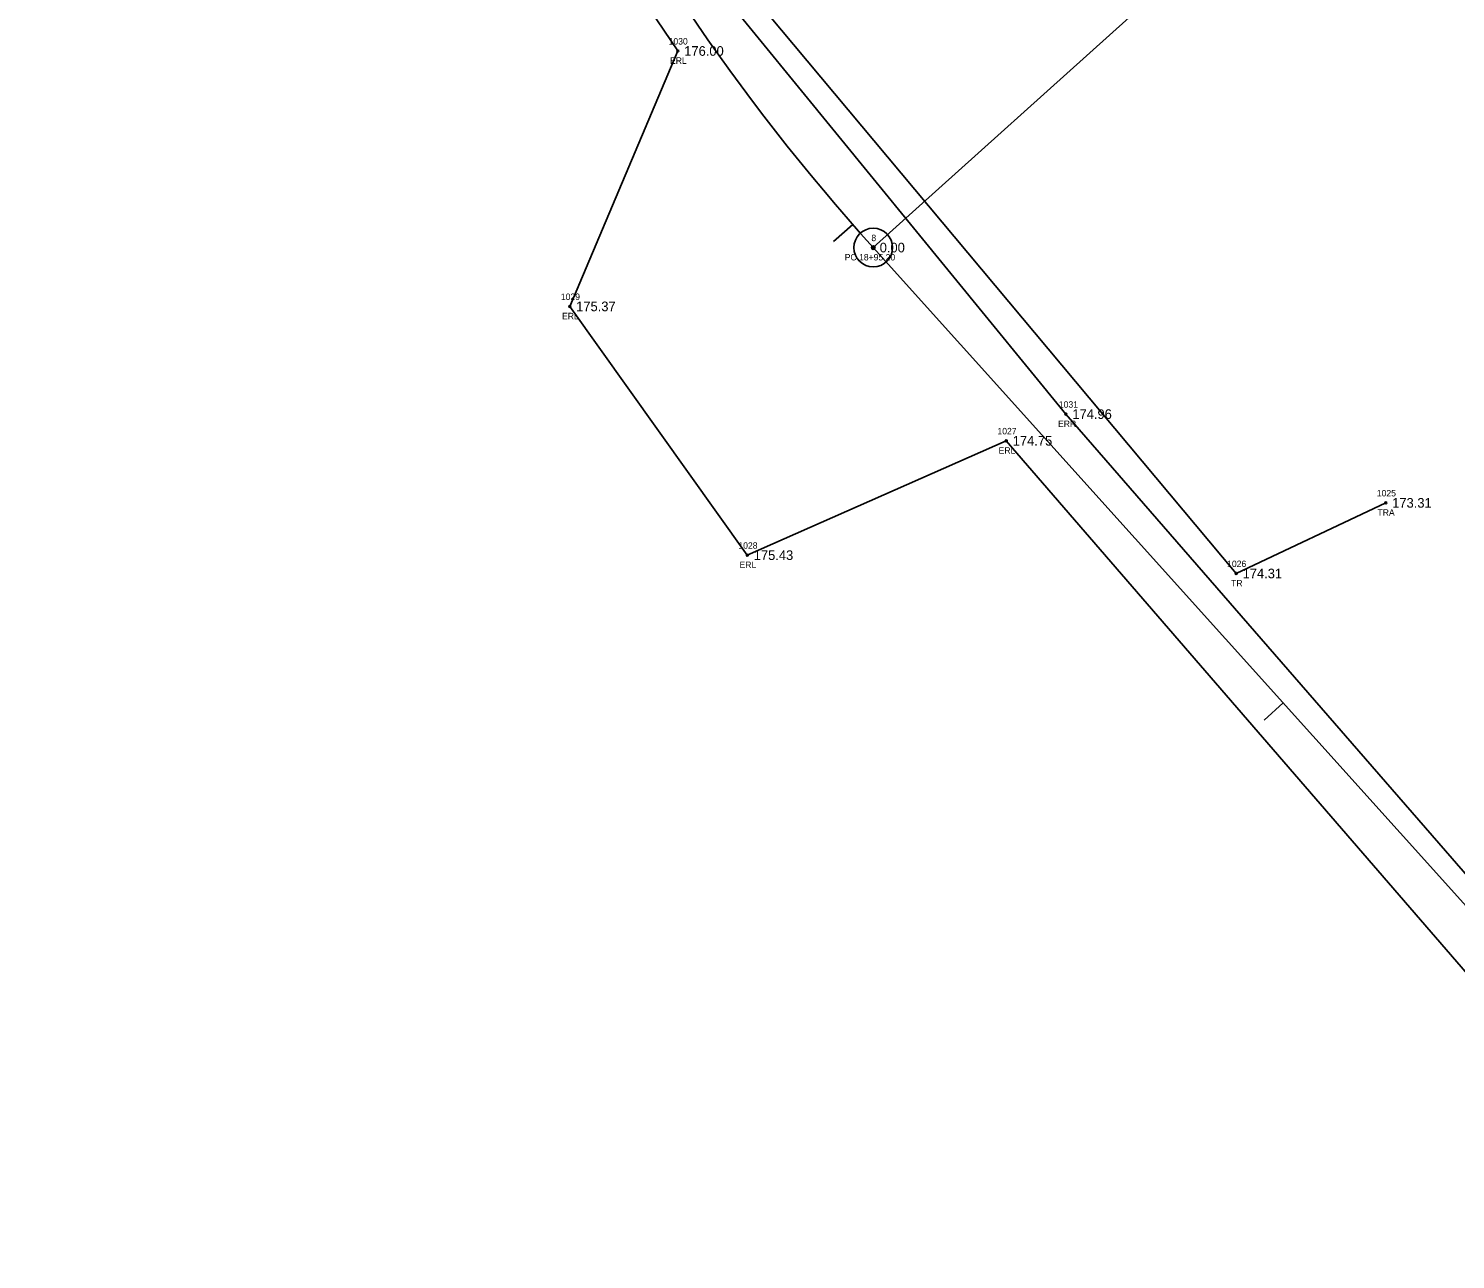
# Model space of a CAD drawing. Extents: x 1970735 to 1971583, y 794736 to 795766.
# Drawn here: x 1970770.6 to 1970992.3, y 795256 to 795447.2 of the extents above; entities that cross this region are included whole.
import ezdxf

# ---------------------------------------------------------------- set-up
doc = ezdxf.new("R2010")
doc.units = 0
for name, color, linetype in [('RD_EX_Road', 7, 'Continuous'), ('RD_EX_Road_txCode', 7, 'Continuous'), ('RD_EX_TX_Road_ELEV', 7, 'Continuous'), ('RD_EX_TX_VEG_ELEV', 7, 'Continuous'), ('RD_EX_VEG', 7, 'Continuous'), ('RD_EX_VEG_txCode', 7, 'Continuous'), ('RD_HC_Cl', 7, 'Continuous'), ('RD_HC_Data', 7, 'Continuous'), ('RD_HC_Data_Tic', 7, 'Continuous'), ('RD_HC_Survey_ELEV', 7, 'Continuous'), ('RD_HC_txCode', 7, 'Continuous'), ('RD_SMD_Locator', 7, 'Continuous')]:
    doc.layers.add(name, color=color, linetype=linetype)

msp = doc.modelspace()

# ---------------------------------------------------------------- linework, layer by layer
at = {"layer": 'RD_EX_Road'}
for points in [[(1971550.5, 794861.13), (1971472.2, 794904.32), (1971401.49, 794943.08), (1971346.58, 794975.73), (1971286.05, 795024.56), (1971217.92, 795079.41), (1971172.76, 795121.06), (1971082.31, 795221.27), (1971017.96, 795288.13), (1970931.75, 795387.33), (1970878.11, 795452.95), (1970856.35, 795489.48), (1970840.29, 795529.45), (1970827.57, 795574.31), (1970814.81, 795635.62), (1970805.04, 795696.13), (1970791.39, 795763.83)], [(1971543.68, 794851.6), (1971507.7, 794872.08), (1971504.76, 794847.96), (1971494.98, 794846.56), (1971488.18, 794883), (1971469.72, 794893.79), (1971395.92, 794934.76), (1971339.47, 794967.38), (1971278.34, 795016.59), (1971212.1, 795072.1), (1971165.04, 795113.96), (1971074.42, 795213.48), (1971010.42, 795281.48), (1970922.49, 795383.19), (1970882.25, 795365.41), (1970854.66, 795404.07), (1970871.45, 795443.76), (1970844.39, 795483.83), (1970828.93, 795526.65), (1970817.76, 795568.61), (1970806.82, 795600.57), (1970787.72, 795602.49), (1970770.58, 795591.56)]]:
    msp.add_lwpolyline(points, dxfattribs=at)
at = {"layer": 'RD_EX_VEG'}
msp.add_lwpolyline([(1970981.44, 795373.54), (1970958.2, 795362.57), (1970881.2, 795454.67), (1970862.6, 795492.82), (1970842.64, 795529.88), (1970855.88, 795543.07)], dxfattribs=at)
at = {"layer": 'RD_HC_Cl'}
msp.add_line((1971124.57, 795165.7), (1970901.81, 795413.21), dxfattribs=at)
msp.add_arc((1971153.66, 795639.87), 338.82, 190.1703, 221.9864, dxfattribs=at)
at = {"layer": 'RD_HC_Data'}
msp.add_line((1970901.81, 795413.21), (1970988.55, 795491.27), dxfattribs=at)
for radius in [3, 0.282]:
    msp.add_circle((1970901.81, 795413.21), radius, dxfattribs=at)
at = {"layer": 'RD_HC_Data_Tic'}
for p, q in [((1970898.63, 795416.8), (1970895.62, 795414.17)), ((1970965.5, 795342.45), (1970962.53, 795339.77))]:
    msp.add_line(p, q, dxfattribs=at)
at = {"layer": 'RD_SMD_Locator'}
for centre in [(1970871.45, 795443.76), (1970901.81, 795413.21), (1970854.66, 795404.07), (1970931.75, 795387.33), (1970922.49, 795383.19), (1970981.44, 795373.54), (1970882.25, 795365.41), (1970958.2, 795362.57)]:
    msp.add_circle(centre, 0.15, dxfattribs=at)

# ---------------------------------------------------------------- texts
at = {"layer": 'RD_EX_Road_txCode'}
for s, p in [('1030', (1970870.02, 795444.76)), ('ERL', (1970870.24, 795441.76)), ('1029', (1970853.28, 795405.07)), ('ERL', (1970853.46, 795402.07)), ('1031', (1970930.65, 795388.33)), ('ERR', (1970930.52, 795385.33)), ('1027', (1970921.11, 795384.19)), ('ERL', (1970921.29, 795381.19)), ('1028', (1970880.86, 795366.41)), ('ERL', (1970881.04, 795363.41))]:
    msp.add_text(s, height=1, dxfattribs=at).set_placement(p)
at = {"layer": 'RD_EX_TX_Road_ELEV'}
for s, p in [('176.00', (1970872.45, 795443.01)), ('175.37', (1970855.66, 795403.32)), ('174.96', (1970932.75, 795386.58)), ('174.75', (1970923.49, 795382.44)), ('175.43', (1970883.25, 795364.66))]:
    msp.add_text(s, height=1.5, dxfattribs=at).set_placement(p)
at = {"layer": 'RD_EX_TX_VEG_ELEV'}
for s, p in [('173.31', (1970982.44, 795372.79)), ('174.31', (1970959.2, 795361.82))]:
    msp.add_text(s, height=1.5, dxfattribs=at).set_placement(p)
at = {"layer": 'RD_EX_VEG_txCode'}
for s, p in [('1025', (1970980.05, 795374.54)), ('TRA', (1970980.15, 795371.54)), ('1026', (1970956.79, 795363.57)), ('TR', (1970957.41, 795360.57))]:
    msp.add_text(s, height=1, dxfattribs=at).set_placement(p)
at = {"layer": 'RD_HC_Survey_ELEV'}
msp.add_text('0.00', height=1.5, dxfattribs=at).set_placement((1970902.82, 795412.46))
at = {"layer": 'RD_HC_txCode'}
for s, p in [('8', (1970901.53, 795414.21)), ('PC 18+95.20', (1970897.38, 795411.21))]:
    msp.add_text(s, height=1, dxfattribs=at).set_placement(p)

doc.saveas('drawing.dxf')
